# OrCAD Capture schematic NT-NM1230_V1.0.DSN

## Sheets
1 Nu-Link-ME V3.0: size A4; title: Nu-Link-Me; rev: 3.0; note: 1
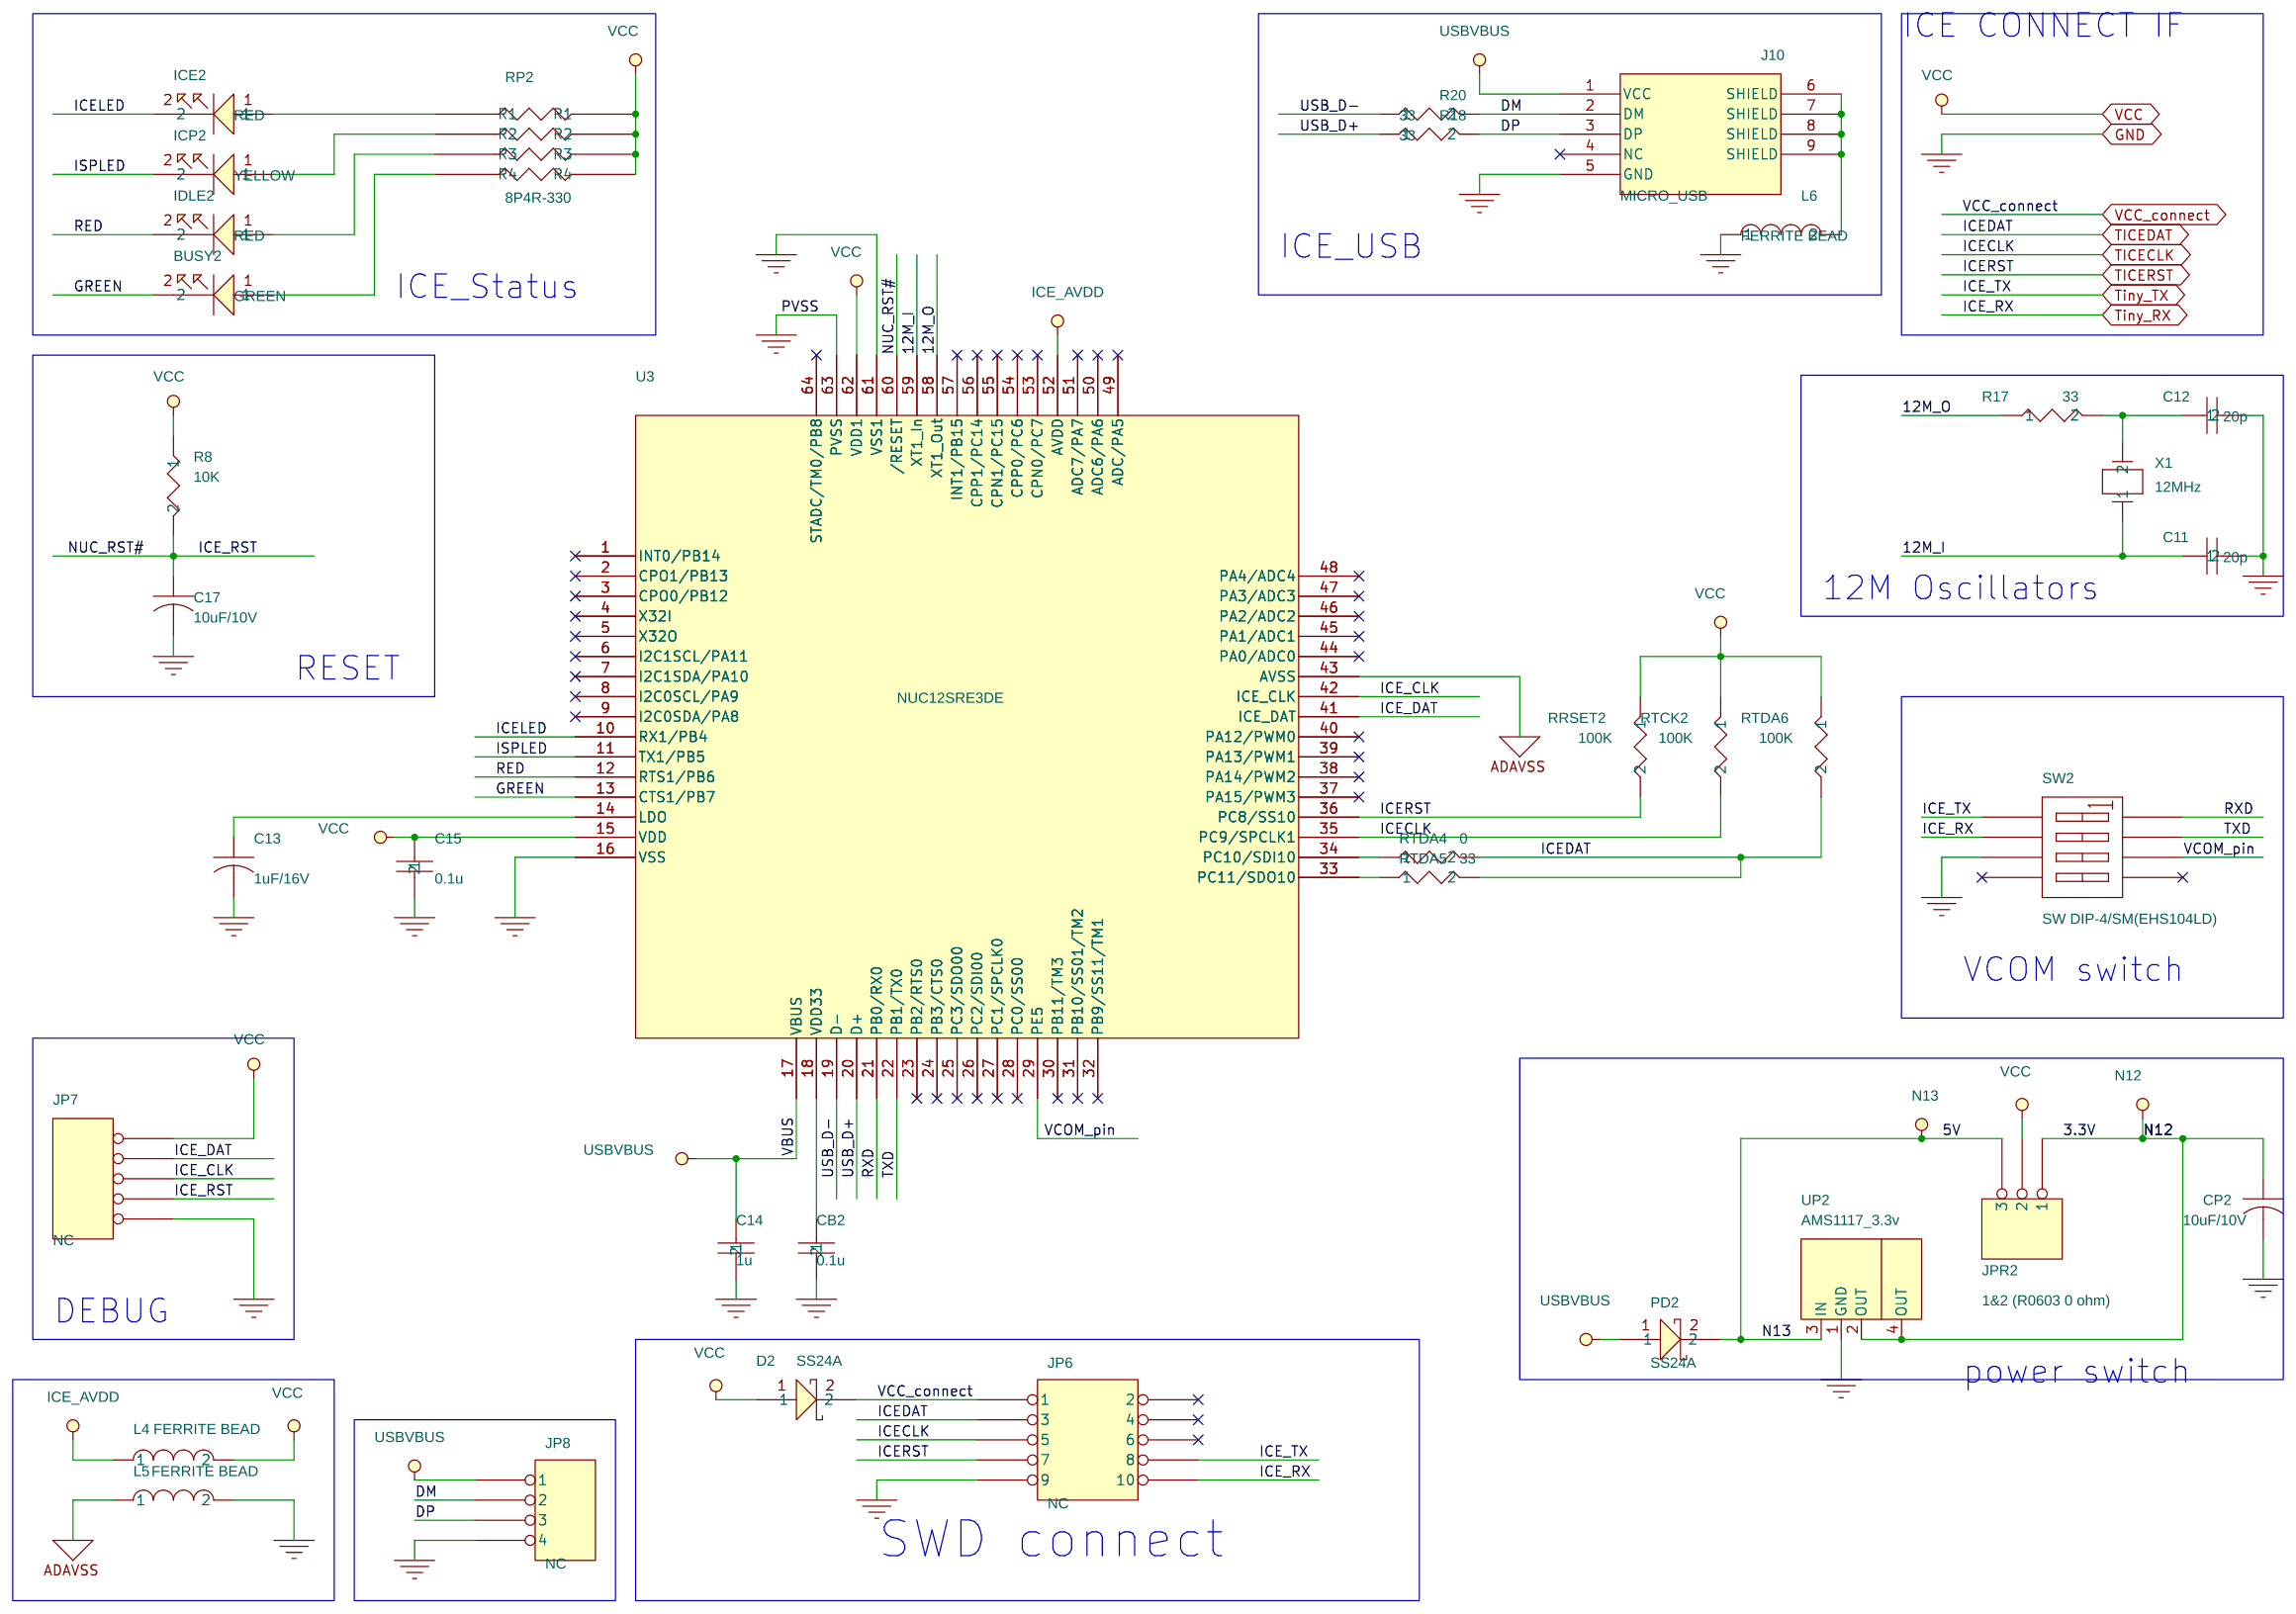
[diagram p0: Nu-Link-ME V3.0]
2 NuTiny-NM1230: size A3; title: NuTiny-EVB-NM1234D; rev: V1.0
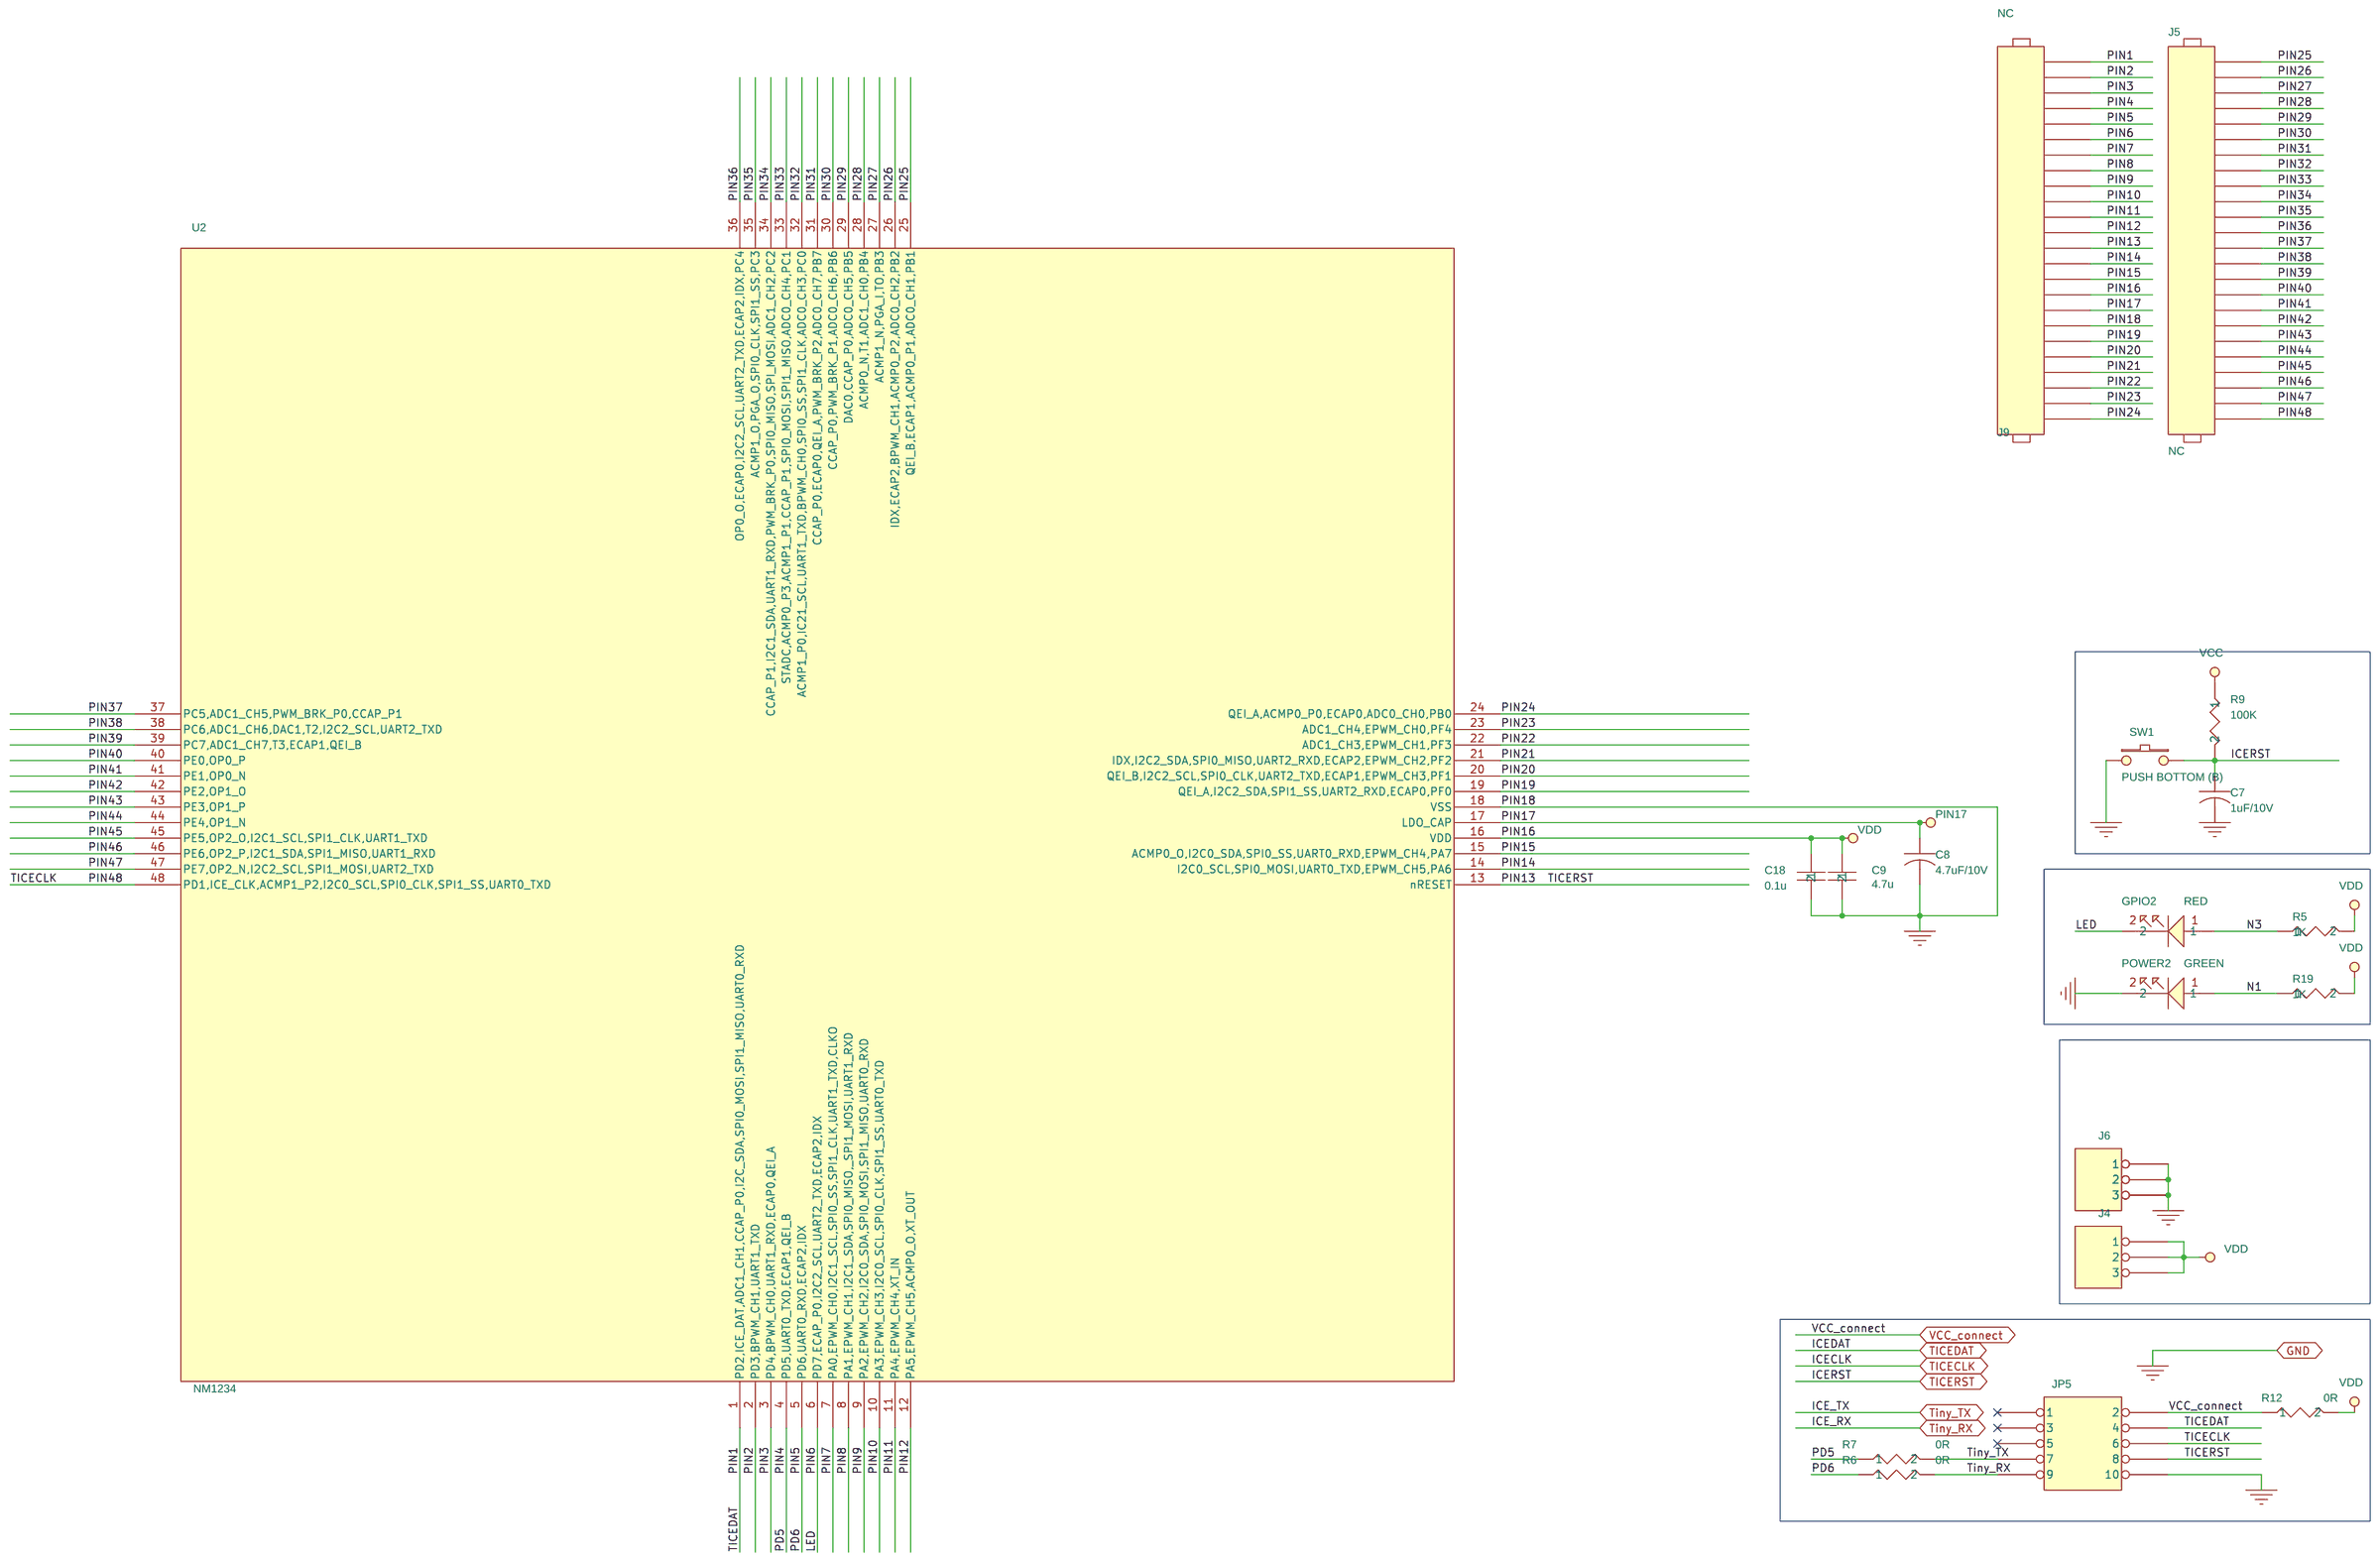
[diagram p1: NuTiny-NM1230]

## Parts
sheet Nu-Link-ME V3.0
BUSY2  GREEN  [LED0805]
C11  20p  [C0603]
C12  20p  [C0603]
C13  1uF/16V  [TANT-A]
C14  1u  [C0603]
C15  0.1u  [C0603]
C17  10uF/10V  [TANT-A]
CB2  0.1u  [C0603]
CP2  10uF/10V  [TANT-A]
D2  SS24A  [RB060L]
ICE2  RED  [LED0805]
ICP2  YELLOW  [LED0805]
IDLE2  RED  [LED0805]
J10  MICRO_USB  [MICRO_USB_AB_LS]
JP6  NC  [HEADER5X2]
JP7  NC  [HEADER05]
JP8  NC  [HEADER04]
JPR2  1&2 (R0603 0 ohm)  [R0603X2]
L4  FERRITE BEAD  [L0603]
L5  FERRITE BEAD  [L0603]
L6  FERRITE BEAD  [L0603]
PD2  SS24A  [RB060L]
R8  10K  [R0603]
R17  33  [R0603]
R18  33  [R0603]
R20  33  [R0603]
RP2  8P4R-330  [8P4RA]
RRSET2  100K  [R0603]
RTCK2  100K  [R0603]
RTDA4  0  [R0603]
RTDA5  33  [R0603]
RTDA6  100K  [R0603]
SW2  SW DIP-4/SM(EHS104LD)  [SW1X4]
U3  NUC12SRE3DE  [NCU120_LQFP_64]
UP2  AMS1117_3.3v  [SOT-223-1]
X1  12MHz  [XTAL\LP\SMD]
sheet NuTiny-NM1230
C7  1uF/10V  [TANT-A]
C8  4.7uF/10V  [TANT-A]
C9  4.7u  [C0603]
C18  0.1u  [C0603]
GPIO2  RED  [LED0805]
J4  header 3x1  [header3]
J5  NC  [HEADER24X1]
J6  header 3x1  [header3]
J9  NC  [HEADER24X1]
JP5  NC  [HEADER5X2]
POWER2  GREEN  [LED0805]
R5  1K  [R0603]
R6  0R  [R0603]
R7  0R  [R0603]
R9  100K  [R0603]
R12  0R  [R0603]
R19  1K  [R0603]
SW1  PUSH BOTTOM (B)  [SW_SMD_HSM]
U2  NM1234  [LQFP-48]

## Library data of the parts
BUSY2 POWER2 = LED_GREEN
C11 = C_20p
C12 = C_20p_1
C8 C13 = C_1uF_16V
C14 C18 = C_1u
C15 = C_0.1u_1
C7 C17 CP2 = C_10uF_10V
CB2 = C_0.1u
D2 = D_SS24A_1
ICE2 = LED_RED_1
ICP2 = LED_YELLOW
GPIO2 IDLE2 = LED_RED
J10 = mini_USB_5pin
JP5 JP6 = HEADER_5X2
JP7 = HEADER_5
JP8 = HEADER_4
J4 JPR2 = HEADER_3
L4 = FERRITE_BEAD
L5 = FERRITE_BEAD_2
L6 = FERRITE_BEAD_1
PD2 = D_SS24A
R8 R12 = R_10K
R17 = R_33_3
R18 = R_33_1
R20 = R_33
RP2 = 8P4R-330
RRSET2 = R_100K_1
RTCK2 = R_100K_2
RTDA4 = R_0
RTDA5 = R_33_2
RTDA6 = R_100K
SW2 = SW_DIP-4_SM
U3 = NCU120_LQFP_1
UP2 = TO-247_Regulator_10
X1 = Xtal_12MHz
C9 = C_1u_1
J5 J9 = HEADER_24
J6 = HEADER_3_1
R5 = R_1K
R6 = R_10K_1
R7 = R_10K_2
R9 = R_10K_3
R19 = R_1K_1
SW1 = PUSH_BOTTOM_(B)
U2 = TF5103

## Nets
3.3V: CP2.1 JPR2.1 UP2.2(OUT) UP2.4(OUT)
5V: JPR2.3 PD2.2 UP2.3(IN)
AVSS: L5.1 U3.43(AVSS)
GND: C7.2 C8.2 C9.2 C11.2 C12.2 C13.2 C14.2 C15.2 C17.2 C18.2 CB2.2 CP2.2 J6.1 J6.2 J6.3 J9.7 J10.5(GND) JP5.10 JP6.9 JP7.5 JP8.4 L5.2 L6.1 POWER2.2 SW1.1 SW2.3(A3) U2.18(VSS) U3.16(VSS) U3.61(VSS1) U3.63(PVSS) UP2.1(GND)
VCC: C15.1 D2.1 JP7.1 JPR2.2 L4.2 R8.1 RP2.2(R1) RP2.4(R2) RP2.6(R3) RP2.8(R4) RRSET2.1 RTCK2.1 RTDA6.1 U3.15(VDD) U3.62(VDD1)
VCC_connect: D2.2 JP5.2 JP6.1 R12.1
VDD: C9.1 C18.1 J4.1 J4.2 J4.3 J9.9 R5.2 R9.1 R12.2 R19.2 U2.16(VDD)
12M_I: C11.1 U3.59(XT1_In) X1.1
12M_O: R17.1 U3.58(XT1_Out)
DM: J10.2(DM) JP8.2 R20.2
DP: J10.3(DP) JP8.3 R18.2
GREEN: BUSY2.2 U3.13(CTS1/PB7)
ICE_AVDD: L4.1 U3.52(AVDD)
ICE_CLK: JP7.3 U3.42(ICE_CLK)
ICE_DAT: JP7.2 U3.41(ICE_DAT)
ICE_RST: C17.1 JP7.4 R8.2 U3.60(/RESET)
ICELED: ICE2.2 U3.10(RX1/PB4)
ICERST: C7.1 J9.12 JP5.8 JP6.7 R9.2 RRSET2.2 SW1.2 U2.13(nRESET) U3.36(PC8/SS10)
ISPLED: ICP2.2 U3.11(TX1/PB5)
LDO_CAP: C8.1 J9.8 U2.17(LDO_CAP)
LED: GPIO2.2 J9.19 U2.6(PD7,ECAP_P0,I2C2_SCL,UART2_TXD,ECAP2,IDX)
N1: POWER2.1 R19.1
N3: GPIO2.1 R5.1
PD5: J9.21 R7.1 U2.4(PD5,UART0_TXD,ECAP1,QEI_B)
PD6: J9.20 R6.1 U2.5(PD6,UART0_RXD,ECAP2,IDX)
PIN2: J9.23 U2.2(PD3,BPWM_CH1,UART1_TXD)
PIN3: J9.22 U2.3(PD4,BPWM_CH0,UART1_RXD,ECAP0,QEI_A)
PIN7: J9.18 U2.7(PA0,EPWM_CH0,I2C1_SCL,SPI0_SS,SPI1_CLK,UART1_TXD,CLKO)
PIN8: J9.17 U2.8(PA1,EPWM_CH1,I2C1_SDA,SPI0_MISO,_SPI1_MOSI,UART1_RXD)
PIN9: J9.16 U2.9(PA2,EPWM_CH2,I2C0_SDA,SPI0_MOSI,SPI1_MISO,UART0_RXD)
PIN10: J9.15 U2.10(PA3,EPWM_CH3,I2C0_SCL,SPI0_CLK,SPI1_SS,UART0_TXD)
PIN11: J9.14 U2.11(PA4,EPWM_CH4,XT_IN)
PIN12: J9.13 U2.12(PA5,EPWM_CH5,ACMP0_O,XT_OUT)
PIN14: J9.11 U2.14(I2C0_SCL,SPI0_MOSI,UART0_TXD,EPWM_CH5,PA6)
PIN15: J9.10 U2.15(ACMP0_O,I2C0_SDA,SPI0_SS,UART0_RXD,EPWM_CH4,PA7)
PIN19: J9.6 U2.19(QEI_A,I2C2_SDA,SPI1_SS,UART2_RXD,ECAP0,PF0)
PIN20: J9.5 U2.20(QEI_B,I2C2_SCL,SPI0_CLK,UART2_TXD,ECAP1,EPWM_CH3,PF1)
PIN21: J9.4 U2.21(IDX,I2C2_SDA,SPI0_MISO,UART2_RXD,ECAP2,EPWM_CH2,PF2)
PIN22: J9.3 U2.22(ADC1_CH3,EPWM_CH1,PF3)
PIN23: J9.2 U2.23(ADC1_CH4,EPWM_CH0,PF4)
PIN24: J9.1 U2.24(QEI_A,ACMP0_P0,ECAP0,ADC0_CH0,PB0)
PIN25: J5.1 U2.25(QEI_B,ECAP1,ACMP0_P1,ADC0_CH1,PB1)
PIN26: J5.2 U2.26(IDX,ECAP2,BPWM_CH1,ACMP0_P2,ADC0_CH2,PB2)
PIN27: J5.3 U2.27(ACMP1_N,PGA_I,TO,PB3)
PIN28: J5.4 U2.28(ACMP0_N,T1,ADC1_CH0,PB4)
PIN29: J5.5 U2.29(DAC0,CCAP_P0,ADC0_CH5,PB5)
PIN30: J5.6 U2.30(CCAP_P0,PWM_BRK_P1,ADC0_CH6,PB6)
PIN31: J5.7 U2.31(CCAP_P0,ECAP0,QEI_A,PWM_BRK_P2,ADC0_CH7,PB7)
PIN32: J5.8 U2.32(ACMP1_P0,IC21_SCL,UART1_TXD,BPWM_CH0,SPI0_SS,SPI1_CLK,ADC0_CH3,PC0)
PIN33: J5.9 U2.33(STADC,ACMP0_P3,ACMP1_P1,CCAP_P1,SPI0_MOSI,SPI1_MISO,ADC0_CH4,PC1)
PIN34: J5.10 U2.34(CCAP_P1,I2C1_SDA,UART1_RXD,PWM_BRK_P0,SPI0_MISO,SPI_MOSI,ADC1_CH2,PC2)
PIN35: J5.11 U2.35(ACMP1_O,PGA_O,SPI0_CLK,SPI1_SS,PC3)
PIN36: J5.12 U2.36(OP0_O,ECAP0,I2C2_SCL,UART2_TXD,ECAP2,IDX,PC4)
PIN37: J5.13 U2.37(PC5,ADC1_CH5,PWM_BRK_P0,CCAP_P1)
PIN38: J5.14 U2.38(PC6,ADC1_CH6,DAC1,T2,I2C2_SCL,UART2_TXD)
PIN39: J5.15 U2.39(PC7,ADC1_CH7,T3,ECAP1,QEI_B)
PIN40: J5.16 U2.40(PE0,OP0_P)
PIN41: J5.17 U2.41(PE1,OP0_N)
PIN42: J5.18 U2.42(PE2,OP1_O)
PIN43: J5.19 U2.43(PE3,OP1_P)
PIN44: J5.20 U2.44(PE4,OP1_N)
PIN45: J5.21 U2.45(PE5,OP2_O,I2C1_SCL,SPI1_CLK,UART1_TXD)
PIN46: J5.22 U2.46(PE6,OP2_P,I2C1_SDA,SPI1_MISO,UART1_RXD)
PIN47: J5.23 U2.47(PE7,OP2_N,I2C2_SCL,SPI1_MOSI,UART2_TXD)
RED: IDLE2.2 U3.12(RTS1/PB6)
RXD: SW2.8(B1) U3.21(PB0/RX0)
TICECLK: J5.24 JP5.6 JP6.5 RTCK2.2 U2.48(PD1,ICE_CLK,ACMP1_P2,I2C0_SCL,SPI0_CLK,SPI1_SS,UART0_TXD) U3.35(PC9/SPCLK1)
TICEDAT: J9.24 JP5.4 JP6.3 RTDA4.2 RTDA5.2 RTDA6.2 U2.1(PD2,ICE_DAT,ADC1_CH1,CCAP_P0,I2C_SDA,SPI0_MOSI,SPI1_MISO,UART0_RXD)
Tiny_RX: JP5.9 JP6.10 R6.2 SW2.2(A2)
Tiny_TX: JP5.7 JP6.8 R7.2 SW2.1(A1)
TXD: SW2.7(B2) U3.22(PB1/TX0)
USB_D+: R18.1 U3.20(D+)
USB_D-: R20.1 U3.19(D-)
USBVBUS: C14.1 J10.1(VCC) JP8.1 PD2.1 U3.17(VBUS)
VCOM_pin: SW2.6(B3) U3.29(PE5)
N00874: BUSY2.1 RP2.7(R4)
N00882: IDLE2.1 RP2.5(R3)
N00906: ICE2.1 RP2.1(R1)
N00938: ICP2.1 RP2.3(R2)
N07793: C12.1 R17.2 X1.2
N16812063: C13.1 U3.14(LDO)
N16812255: CB2.1 U3.18(VDD33)
N16812376: RTDA5.1 U3.33(PC11/SDO10)
N17861502: RTDA4.1 U3.34(PC10/SDI10)
N18771284: J10.6(SHIELD) J10.7(SHIELD) J10.8(SHIELD) J10.9(SHIELD) L6.2

Not connected (* = marked no-connect by the designer): J10 4(NC)*; JP5 1* 3* 5*; JP6 2* 4* 6*; SW2 4(A4)* 5(B4)*; U3 1(INT0/PB14)* 2(CPO1/PB13)* 3(CPO0/PB12)* 4(X32I)* 5(X32O)* 6(I2C1SCL/PA11)* 7(I2C1SDA/PA10)* 8(I2C0SCL/PA9)* 9(I2C0SDA/PA8)* 23(PB2/RTS0)* 24(PB3/CTS0)* 25(PC3/SDO00)* 26(PC2/SDI00)* 27(PC1/SPCLK0)* 28(PC0/SS00)* 30(PB11/TM3)* 31(PB10/SS01/TM2)* 32(PB9/SS11/TM1)* 37(PA15/PWM3)* 38(PA14/PWM2)* 39(PA13/PWM1)* 40(PA12/PWM0)* 44(PA0/ADC0)* 45(PA1/ADC1)* 46(PA2/ADC2)* 47(PA3/ADC3)* 48(PA4/ADC4)* 49(ADC/PA5)* 50(ADC6/PA6)* 51(ADC7/PA7)* 53(CPN0/PC7)* 54(CPP0/PC6)* 55(CPN1/PC15)* 56(CPP1/PC14)* 57(INT1/PB15)* 64(STADC/TM0/PB8)*

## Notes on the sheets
sheet 1
- ICE CONNECT IF
- ICE_USB
- ICE_Status
- 12M Oscillators
- RESET
- VCOM switch
- DEBUG
- power switch
- SWD connect
